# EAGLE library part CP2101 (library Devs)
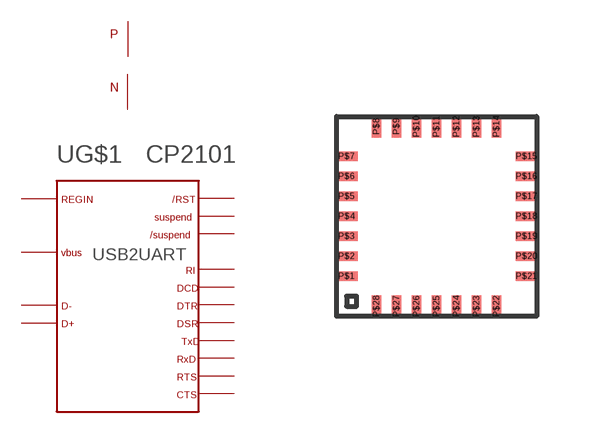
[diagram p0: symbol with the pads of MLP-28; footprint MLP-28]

Designator prefix -; gates G$1=CP2101 G$2=PWR G$3=NC G$4=NC G$5=NC G$6=NC G$7=NC G$8=NC G$9=NC G$10=NC G$11=NC G$12=NC G$13=NC

## CP2101  [MLP-28]
P$1  G$1:P$DCD  in
P$2  G$1:P$RI  in
P$3  G$2:P$N  sup
P$4  G$1:P$D+
P$5  G$1:P$D-
P$6  G$2:P$P  pwr
P$7  G$1:P$REGIN  sup
P$8  G$1:P$VBUS  in
P$9  G$1:P$RTS  out
P$10  G$11:P$NC  nc
P$11  G$1:P$/SUSSPEND  out
P$12  G$1:P$SUSSPEND  out
P$13  G$13:P$NC  nc
P$14  G$12:P$NC  nc
P$15  G$3:P$NC  nc
P$16  G$4:P$NC  nc
P$17  G$5:P$NC  nc
P$18  G$6:P$NC  nc
P$19  G$7:P$NC  nc
P$20  G$8:P$NC  nc
P$21  G$9:P$NC  nc
P$22  G$10:P$NC  nc
P$23  G$1:P$CTS  in
P$24  G$1:P$RST  in
P$25  G$1:P$RXD  in
P$26  G$1:P$TXD  out
P$27  G$1:P$DSR  in
P$28  G$1:P$DTR  out

## Footprint MLP-28 (pad centres in mm)
smd 0.55 x 0.23: P$1 -2.25,-1.5; P$2 -2.25,-1; P$3 -2.25,-0.5; P$4 -2.25,0; P$5 -2.25,0.5; P$6 -2.25,1; P$7 -2.25,1.5; P$15 2.25,1.5; P$16 2.25,1; P$17 2.25,0.5; P$18 2.25,0; P$19 2.25,-0.5; P$20 2.25,-1; P$21 2.25,-1.5
smd 0.23 x 0.55: P$8 -1.5,2.25; P$9 -1,2.25; P$10 -0.5,2.25; P$11 0,2.25; P$12 0.5,2.25; P$13 1,2.25; P$14 1.5,2.25; P$22 1.5,-2.25; P$23 1,-2.25; P$24 0.5,-2.25; P$25 0,-2.25; P$26 -0.5,-2.25; P$27 -1,-2.25; P$28 -1.5,-2.25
